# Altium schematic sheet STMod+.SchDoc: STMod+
size A4; CompanyName: STMicroelectronics; Organization: Microcontrollers Division; DocumentNumber: 17; SheetNumber: 14; SheetTotal: 19
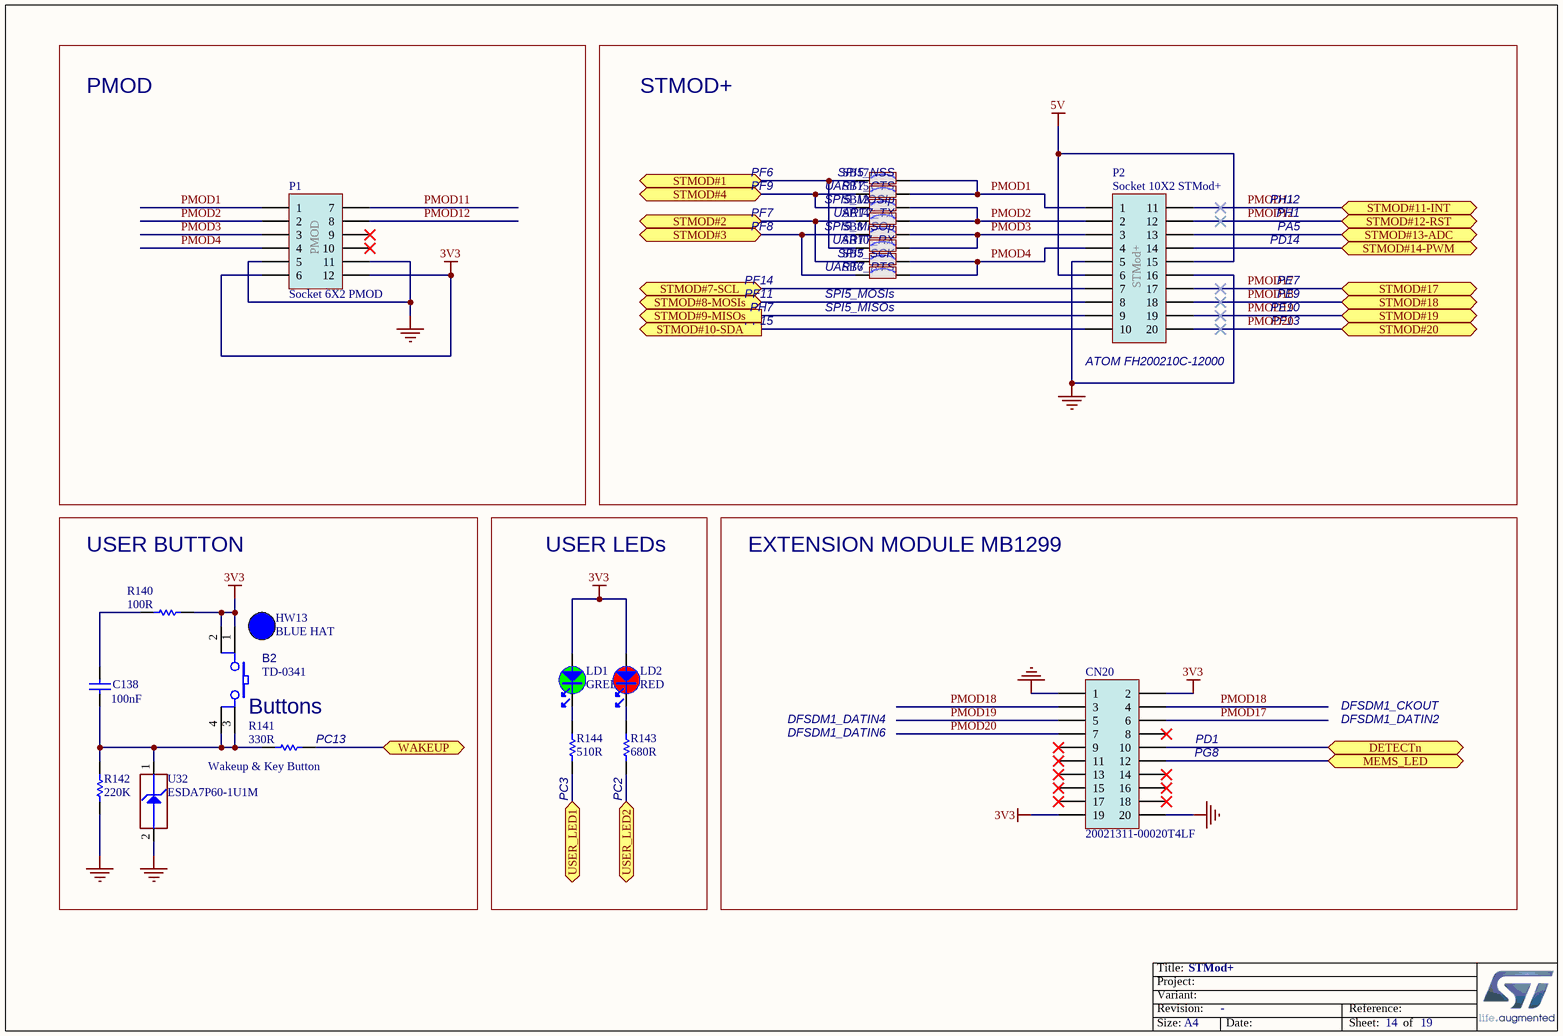
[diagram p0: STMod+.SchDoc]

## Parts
B2  Manufacturer_Part_Number: TD-0341  [SWI_WEALTHMETAL_TD-0341_4P_BLUE]  (hidden comment: SW-PUSH-CMS)
C138  value 100nF  [C0402]  (hidden comment: Capacitor)
CN20  value 20021311-00020T4LF  [CON_FCI_20021311-XXX20XXLF]  (hidden comment: Socket 10x2)
HW13  value BLUE HAT  (hidden comment: BUTTON_HAT_BLUE)  (mechanical)
LD1  value GREEN  [LED_0603_GREEN]  (hidden comment: LED_green)
LD2  value RED  [LED_0603_RED]  (hidden comment: LED_red)
P1  Socket 6X2 PMOD  [CON_SAMTEC_SSW-106-02-F-D-RA__PMOD]
P2  Socket 10X2 STMod+  [CON_SAMTEC_SQT-110-01-F-D-RA__STMOD+]
R140  value 100R  [R0402]  (hidden comment: Resistor)
R141  value 330R  [R0402]  (hidden comment: Resistor)
R142  value 220K  [R0402]  (hidden comment: Resistor)
R143  value 680R  [R0603]  (hidden comment: Resistor)
R144  value 510R  [R0603]  (hidden comment: Resistor)
SB6  SB_ON  [SOLDER-BRIDGE_R0603-0R]  (value not drawn)
SB7  SB_ON  [SOLDER-BRIDGE_R0603-0R]  (value not drawn)
SB8  SB_ON  [SOLDER-BRIDGE_R0603-0R]  (value not drawn)
SB10  SB_ON  [SOLDER-BRIDGE_R0603-0R]  (value not drawn)
SB12  SB_ON  [SOLDER-BRIDGE_R0603-0R]  (value not drawn)
SB14  SB_ON  [SOLDER-BRIDGE_R0603-0R]  (value not drawn)
SB15  SB_ON  [SOLDER-BRIDGE_R0603-0R]  (value not drawn)
SB17  SB_ON  [SOLDER-BRIDGE_R0603-0R]  (value not drawn)
U32  value ESDA7P60-1U1M  [ESD_QFN2_1P6X1_P125]  (hidden comment: ESD-TRANSIL)

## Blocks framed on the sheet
PMOD: P1
STMOD+: P2 SB6-SB8 SB10 SB12 SB14 SB15 SB17
USER LEDs: LD1 LD2 R143 R144
EXTENSION MODULE MB1299: CN20

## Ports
DETECTn, MEMS_LED, STMOD#1, STMOD#2, STMOD#3, STMOD#4, STMOD#7-SCL, STMOD#8-MOSIs, STMOD#9-MISOs (out), STMOD#10-SDA (out), STMOD#11-INT, STMOD#12-RST, STMOD#13-ADC, STMOD#14-PWM, STMOD#17, STMOD#18, STMOD#19, STMOD#20, USER_LED1, USER_LED2, WAKEUP

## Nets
3V3: B2.1 B2.2 CN20.2 CN20.19 LD1.1 LD2.1 P1.6 P1.12 R140.2
5V: P2.6 P2.15
GND: CN20.1 CN20.20 P1.5 P1.11 P2.5 P2.16 R142.1 U32.2(GND)
DETECTn: CN20.10 ; port DETECTn
MEMS_LED: CN20.12 ; port MEMS_LED
PMOD1: P1.1 P2.1 SB15.2 SB17.2
PMOD2: P1.2 P2.2 SB12.2 SB14.2
PMOD3: P1.3 P2.3 SB8.2 SB10.2
PMOD4: P1.4 P2.4 SB6.2 SB7.2
PMOD11: P1.7 P2.11 ; port STMOD#11-INT
PMOD12: P1.8 P2.12 ; port STMOD#12-RST
PMOD17: CN20.6 P2.17 ; port STMOD#17
PMOD18: CN20.3 CN20.4 P2.18 ; port STMOD#18
PMOD19: CN20.5 P2.19 ; port STMOD#19
PMOD20: CN20.7 P2.20 ; port STMOD#20
STMOD#1: SB10.1 SB17.1 ; port STMOD#1
STMOD#2: SB7.1 SB14.1 ; port STMOD#2
STMOD#3: SB6.1 SB8.1 ; port STMOD#3
STMOD#4: SB12.1 SB15.1 ; port STMOD#4
STMOD#7-SCL: P2.7 ; port STMOD#7-SCL
STMOD#8-MOSIs: P2.8 ; port STMOD#8-MOSIs
STMOD#9-MISOs: P2.9 ; port STMOD#9-MISOs
STMOD#10-SDA: P2.10 ; port STMOD#10-SDA
STMOD#13-ADC: P2.13 ; port STMOD#13-ADC
STMOD#14-PWM: P2.14 ; port STMOD#14-PWM
USER_LED1: R144.1 ; port USER_LED1
USER_LED2: R143.1 ; port USER_LED2
WAKEUP: R141.2 ; port WAKEUP
NetB2_3: B2.3 B2.4 C138.2 R141.1 R142.2 U32.1(IO1)
NetC138_1: C138.1 R140.1
NetLD1_2: LD1.2 R144.2
NetLD2_2: LD2.2 R143.2

Not connected (* = marked no-connect by the designer): CN20 8* 9* 11* 13* 14* 15* 16* 17* 18*; P1 9* 10*

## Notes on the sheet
- PF6
- (near SB17) SPI5_NSS
- PF9
- PF7
- PF8
- UART7_CTS
- SPI5_MOSIp
- UART7_TX
- SPI5_MISOp
- UART7_RX
- PH1
- PA5
- PH12
- PD14
- PF14
- PF11
- PH7
- SPI5_SCK
- UART7_RTS
- (near SB6) SPI5_MOSIs
- SPI5_MISOs
- PE7
- PE9
- PE10
- PF15
- (near P2) ATOM FH200210C-12000
- PF13
- USER BUTTON
- (near B2) Buttons
- DFSDM1_CKOUT
- (near R141) Wakeup & Key Button
- (near R141) PC13
- DFSDM1_DATIN4
- DFSDM1_DATIN6
- PD1
- PG8
- DFSDM1_DATIN2
- (near R144) PC3
- (near R143) PC2

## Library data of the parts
B2 = MCD-00002: Non-Open Push-Button 0.1A 24V; Part_Type: Misc; Manufacturer: WEALTHMETAL; Value: SWITCH; Provided_By: SUBCO
C138 = MCD-00102: Capacitor, MLCC, 100nF, 16V, X7R, 10%, 0402, T=0,5mm; Manufacturer_Part_Number: CC0402KRX7R7BB104; Manufacturer: YAGEO; Alternate_Manufacturer_Part_Number: GCM155R71C104KA55D; Alternate_Manufacturer: MURATA; Provided_By: SUBCO
CN20 = MCD-00147: Socket for MB1299, 10x2, 1.27mm, VR, TH, Height 4.30mm/2.40mm; Part_Type: Connector; Manufacturer: FCI; Alternate_Manufacturer_Part_Number: 234220S1410; Alternate_Manufacturer: JIUBABA; Provided_By: SUBCO
HW13 = MCD-00634: Blue Hat for switch TD0341X-G01-BLU; Part_Type: Mechanical; Manufacturer_Part_Number: 988.16.09.3.00002_SH-517; Manufacturer: JIUBABA; Provided_By: SUBCO
LD1 = MCD-00050: LED, Green, 0603; Part_Type: Display; Manufacturer_Part_Number: 19-213SYGC/S530-E2/TR8; Manufacturer: EVERLIGHT; Provided_By: SUBCO
LD2 = MCD-00049: LED, Red, 0603; Manufacturer_Part_Number: 19-213-R6C-AP1Q2B/3T; Manufacturer: EVERLIGHT; Part_Type: Display; Provided_By: SUBCO
P1 = MCD-00308: Socket, 6x2, 2.54mm, TH, RA, Height 8.51mm/7.62mm; Part_Type: Connector; Manufacturer_Part_Number: SSW-106-02-F-D-RA; Manufacturer: SAMTEC; Provided_By: SUBCO
P2 = MCD-00309: Socket 10x2, 2.00mm, RA, TH, Height 6.35mm/2.29mm; Part_Type: Connector; Manufacturer_Part_Number: SQT-110-01-F-D-RA; Manufacturer: SAMTEC; Alternate_Manufacturer_Part_Number: FH200020C-12300; Alternate_Manufacturer: JIUBABA; Provided_By: SUBCO
R140 = MCD-00119: Resistor,100R,0402,1%,1/16W; Manufacturer_Part_Number: RC0402FR-07100RL; Manufacturer: YAGEO; Provided_By: SUBCO
R141 = MCD-00062: Resistor,330R,0402,1%,1/16W; Manufacturer_Part_Number: RC0402FR-07330RL; Manufacturer: YAGEO; Provided_By: SUBCO
R142 = MCD-00164: Resistor,220K,0402,1%,1/16W; Manufacturer_Part_Number: RC0402FR-07220KL; Manufacturer: YAGEO; Provided_By: SUBCO
R143 = MCD-00508: Resistor,680R,0603,1%,1/10W; Manufacturer_Part_Number: RC0603FR-07680RL; Manufacturer: YAGEO; ECCN_US: EAR99; ECCN_EU: NEC; Provided_By: SUBCO
R144 = MCD-00225: Resistor,510R,0603,1%,1/10W; Manufacturer_Part_Number: RC0603FR-07510RL; Manufacturer: YAGEO; Provided_By: SUBCO
SB6-SB8 SB10 SB12 SB14 SB15 SB17 = MCD-00071: Solder Bridge ON; Part_Type: Mechanical; Manufacturer_Part_Number: RC0603JR-070RL; Manufacturer: YAGEO; Provided_By: SUBCO
U32 = MCD-00251: High power transient voltage suppressor, 7V breakdown; Part_Type: Diode; Manufacturer: STMICROELECTRONICS; BMS_Part_Number: 9179042; Provided_By: SUBCO with ST control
